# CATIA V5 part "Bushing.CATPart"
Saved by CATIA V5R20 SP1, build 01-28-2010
Part number: Bushing
Bounding box of the stored display mesh (mm): x -13.45 to 13.45, y 0 to 63, z -13.45 to 13.45
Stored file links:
  D:\v5_r20\psrt_files_downloaded\c14\c14-catia-v5r20-figr-14-26 & 27\Part & Asm\Bushing.CATPart
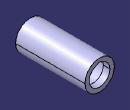
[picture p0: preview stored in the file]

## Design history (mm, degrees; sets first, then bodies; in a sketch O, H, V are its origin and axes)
Body1 (main body)
  Sketch1 on zx-plane, origin (0, 0, 0), H (-1, 0, 0), V (0, 0, 1)
    circle A1 centre (0, 0) radius 9.5
    circle A2 centre (0, 0) radius 13.45
    radius A1 = 9.5
    radius A2 = 13.45
  Pad1: profile Sketch1, direction (0, 1, 0), length 63
  Sketch2 on face of Pad1, origin (0, 63, 0), H (-1, 0, 0), V (0, 0, 1)
    line L1 (-1.5, 9.3808) -> (1.5, 9.3808)
    line L2 (1.5, 9.3808) -> (1.5, 10.1808)
    line L3 (1.5, 10.1808) -> (-1.5, 10.1808)
    line L4 (-1.5, 10.1808) -> (-1.5, 9.3808)
    point P2 (1.5, 9.3808)
    reference projected circle E1 centre (0, 0) radius 9.5 from edge of Pad1
    length L3 = 3
    length L2 = 0.8
    distance V L4 = 1.5
    horizontal: L1 H, L3 H
    vertical: L2 V, L4 V
    coincidence: P2 E1
  Pocket1: profile Sketch2, direction (0, -1, 0), through (limit type 6)
  Sketch3 on xy-plane, origin (0, 0, 0), H (1, 0, 0), V (0, 1, 0)
    line L1 (9.5, 57) -> (10.3, 57)
    line L2 (10.3, 57) -> (10.3, 49)
    line L3 (10.3, 49) -> (9.5, 49)
    line L4 (9.5, 49) -> (9.5, 57)
    reference projected line E1 (13.45, 63) -> (-13.45, 63) from edge of Pad1
    length L2 = 8
    length L1 = 0.8
    distance L3 E1 = 14
    distance V L4 = 9.5
    horizontal: L1 H, L3 H
    vertical: L2 V, L4 V
  Groove1: profile Sketch3, axis axis of face of Pad1, angle 360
